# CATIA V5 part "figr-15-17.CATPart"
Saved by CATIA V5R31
Part number: Part1
Bounding box of the stored display mesh (mm): x -46.56 to 46.56, y -26.965 to 25.965, z 0 to 40
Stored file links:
  D:\PROJECTS\Project 2021\US EDITION\CATIA V5 6R 2021\Resources\Part Files\c15_catia_v5_6r2021_prt\figr-15-17.CATPart
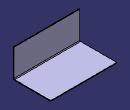
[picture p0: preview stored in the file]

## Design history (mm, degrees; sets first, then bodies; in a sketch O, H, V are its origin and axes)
SheetMetalParameters1: Thickness 1, BendRadius 1, KFactor 0.325257 {= log(min(100,max(20*SheetMetalParameters1.BendRadius,SheetMetalParameters1.Thickness)/SheetMetalParameters1.Thickness))/log(100)/2}, ReliefRadialLength 1, ReliefAxialLength 2, MinimumBendRadius 0
Body1 (main body)
  Sketch1 on xy-plane, origin (0, 0, 0), H (1, 0, 0), V (0, 1, 0)
    line L1 (-46.5596, 25.9646) -> (46.5596, 25.9646)
    line L2 (46.5596, 25.9646) -> (46.5596, -25.9646)
    line L3 (46.5596, -25.9646) -> (-46.5596, -25.9646)
    line L4 (-46.5596, -25.9646) -> (-46.5596, 25.9646)
    horizontal: L1 H, L3 H
    vertical: L2 V, L4 V
    symmetry: L1 L3 H, L4 L2 V
  Wall1: Thickness 1, Profile Sketch1
  d_NewWallOnEdge1: NewWallOnEdge_Edge edge [face of Wall1 | face of Wall1], NewWallOnEdge_Length 40, NewWallOnEdge_HeightLimitOffset 0, NewWallOnEdge_WidthOffset1 0, NewWallOnEdge_WidthOffset2 0, NewWallOnEdge_Angle 90, NewWallOnEdge_BendRadiusValue 1 {= SheetMetalParameters1.BendRadius}, NewWallOnEdge_BendTable SheetMetalParameters1, KFacteur 0.325257 {= log(min(100,max(20*d_NewWallOnEdge1.Radius,SheetMetalParameters1.Thickness)/SheetMetalParameters1.Thickness))/log(100)/2}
